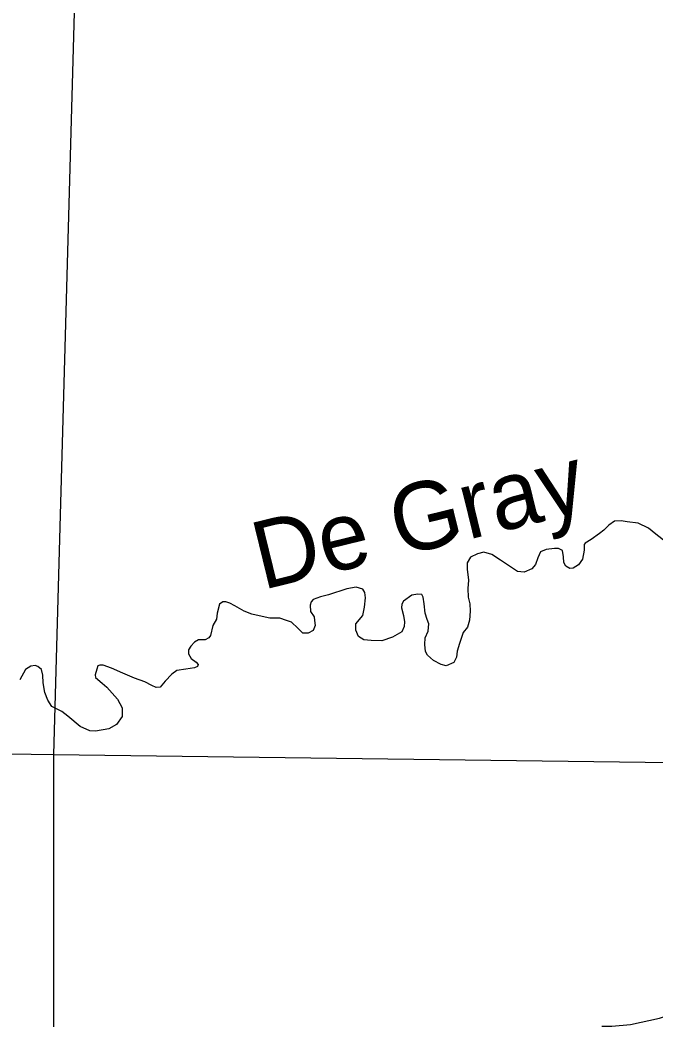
# Model space of a CAD drawing. Extents: x 813775 to 1157140, y 1757555 to 1979907.
# Drawn here: x 943252 to 951173, y 1862069 to 1874542 of the extents above; entities that cross this region are included whole.
import ezdxf

# ---------------------------------------------------------------- set-up
doc = ezdxf.new("R2010")
doc.units = 0
for name, color, linetype in [('Level 31', 7, 'Continuous'), ('Level 35', 7, 'Continuous'), ('Level 5', 7, 'Continuous')]:
    doc.layers.add(name, color=color, linetype=linetype)

msp = doc.modelspace()

# ---------------------------------------------------------------- linework, layer by layer
at = {"layer": 'Level 31'}
msp.add_lwpolyline([(950511, 1861991), (950634, 1861991), (950869, 1862012), (951230, 1862093), (951496, 1862179)], dxfattribs=at)
at = {"layer": 'Level 35'}
for points in [[(950752, 1868295), (950668, 1868289), (950597, 1868239), (950533, 1868178), (950480, 1868138), (950376, 1868063), (950302, 1868018), (950291, 1868000), (950291, 1867928), (950270, 1867819), (950217, 1867747), (950153, 1867705), (950111, 1867699), (950060, 1867731), (950036, 1867774), (950031, 1867848), (950020, 1867925), (949970, 1867952), (949919, 1867952), (949816, 1867936), (949744, 1867907), (949712, 1867835), (949683, 1867752), (949635, 1867697), (949540, 1867654), (949457, 1867665), (949370, 1867723), (949245, 1867803), (949136, 1867877), (949038, 1867904), (948958, 1867885), (948873, 1867840), (948828, 1867771)], [(951738, 1867995), (951565, 1867938), (951472, 1867930), (951390, 1867957), (951316, 1868024), (951185, 1868130), (951092, 1868204), (950965, 1868268), (950827, 1868284), (950752, 1868295)], [(948828, 1867771), (948829, 1867693), (948847, 1867557), (948837, 1867451), (948842, 1867344), (948863, 1867259), (948868, 1867169), (948860, 1867055), (948834, 1866970), (948778, 1866903), (948736, 1866765), (948706, 1866669), (948696, 1866595), (948664, 1866528), (948568, 1866488), (948505, 1866502), (948409, 1866555), (948335, 1866619), (948311, 1866664), (948303, 1866754), (948308, 1866834), (948343, 1866919), (948351, 1867012), (948329, 1867065), (948305, 1867145), (948292, 1867259)], [(948292, 1867259), (948282, 1867344), (948263, 1867376), (948213, 1867379), (948139, 1867366), (948035, 1867294), (948014, 1867254), (948009, 1867211), (948035, 1867116), (948048, 1867036), (948043, 1866978), (948014, 1866911), (947900, 1866845), (947767, 1866799), (947634, 1866802), (947541, 1866810), (947475, 1866853), (947440, 1866930), (947440, 1867012), (947528, 1867113), (947549, 1867219), (947562, 1867334), (947554, 1867400), (947530, 1867443), (947445, 1867467), (947329, 1867445), (947100, 1867374), (947002, 1867347)], [(947002, 1867347), (946907, 1867312), (946883, 1867283), (946870, 1867243), (946875, 1867166), (946920, 1867097), (946925, 1867052), (946933, 1866990), (946909, 1866927), (946848, 1866892), (946779, 1866895), (946716, 1866956), (946639, 1867030), (946577, 1867052), (946495, 1867081), (946370, 1867081), (946235, 1867110), (946142, 1867129), (946049, 1867169), (945932, 1867235), (945868, 1867270), (945821, 1867283), (945783, 1867283), (945741, 1867254), (945712, 1867142), (945701, 1867070), (945659, 1866988), (945629, 1866865), (945608, 1866834), (945563, 1866812), (945478, 1866810), (945430, 1866780), (945382, 1866733), (945353, 1866687), (945353, 1866637), (945385, 1866578), (945451, 1866531), (945475, 1866504), (945465, 1866480), (945430, 1866461), (945321, 1866443), (945210, 1866427), (945146, 1866384), (945064, 1866297), (945000, 1866222), (944949, 1866217), (944896, 1866243), (944809, 1866289), (944681, 1866334), (944535, 1866395), (944394, 1866459), (944288, 1866493), (944248, 1866493), (944224, 1866485), (944209, 1866445), (944190, 1866374), (944195, 1866339), (944275, 1866270), (944336, 1866220)], [(944455, 1865755), (944362, 1865700), (944195, 1865670), (944123, 1865676), (944001, 1865729), (943850, 1865859), (943773, 1865915), (943648, 1865981), (943597, 1866058), (943560, 1866154), (943542, 1866276), (943536, 1866369), (943518, 1866441), (943475, 1866478), (943441, 1866489), (943385, 1866481), (943321, 1866441), (943249, 1866311)], [(944336, 1866220), (944469, 1866069), (944525, 1865963), (944525, 1865854), (944455, 1865755)]]:
    msp.add_lwpolyline(points, dxfattribs=at)
at = {"layer": 'Level 5'}
for points in [[(943943, 1875237), (943671, 1865382)], [(933044, 1865537), (943671, 1865382)], [(943671, 1865382), (943668, 1861482)], [(943671, 1865382), (954261, 1865245)]]:
    msp.add_lwpolyline(points, dxfattribs=at)

# ---------------------------------------------------------------- texts
at = {"layer": 'Level 35'}
msp.add_text('De Gray', height=844.8, rotation=13.758, dxfattribs=at).set_placement((946276, 1867431))

doc.saveas('drawing.dxf')
